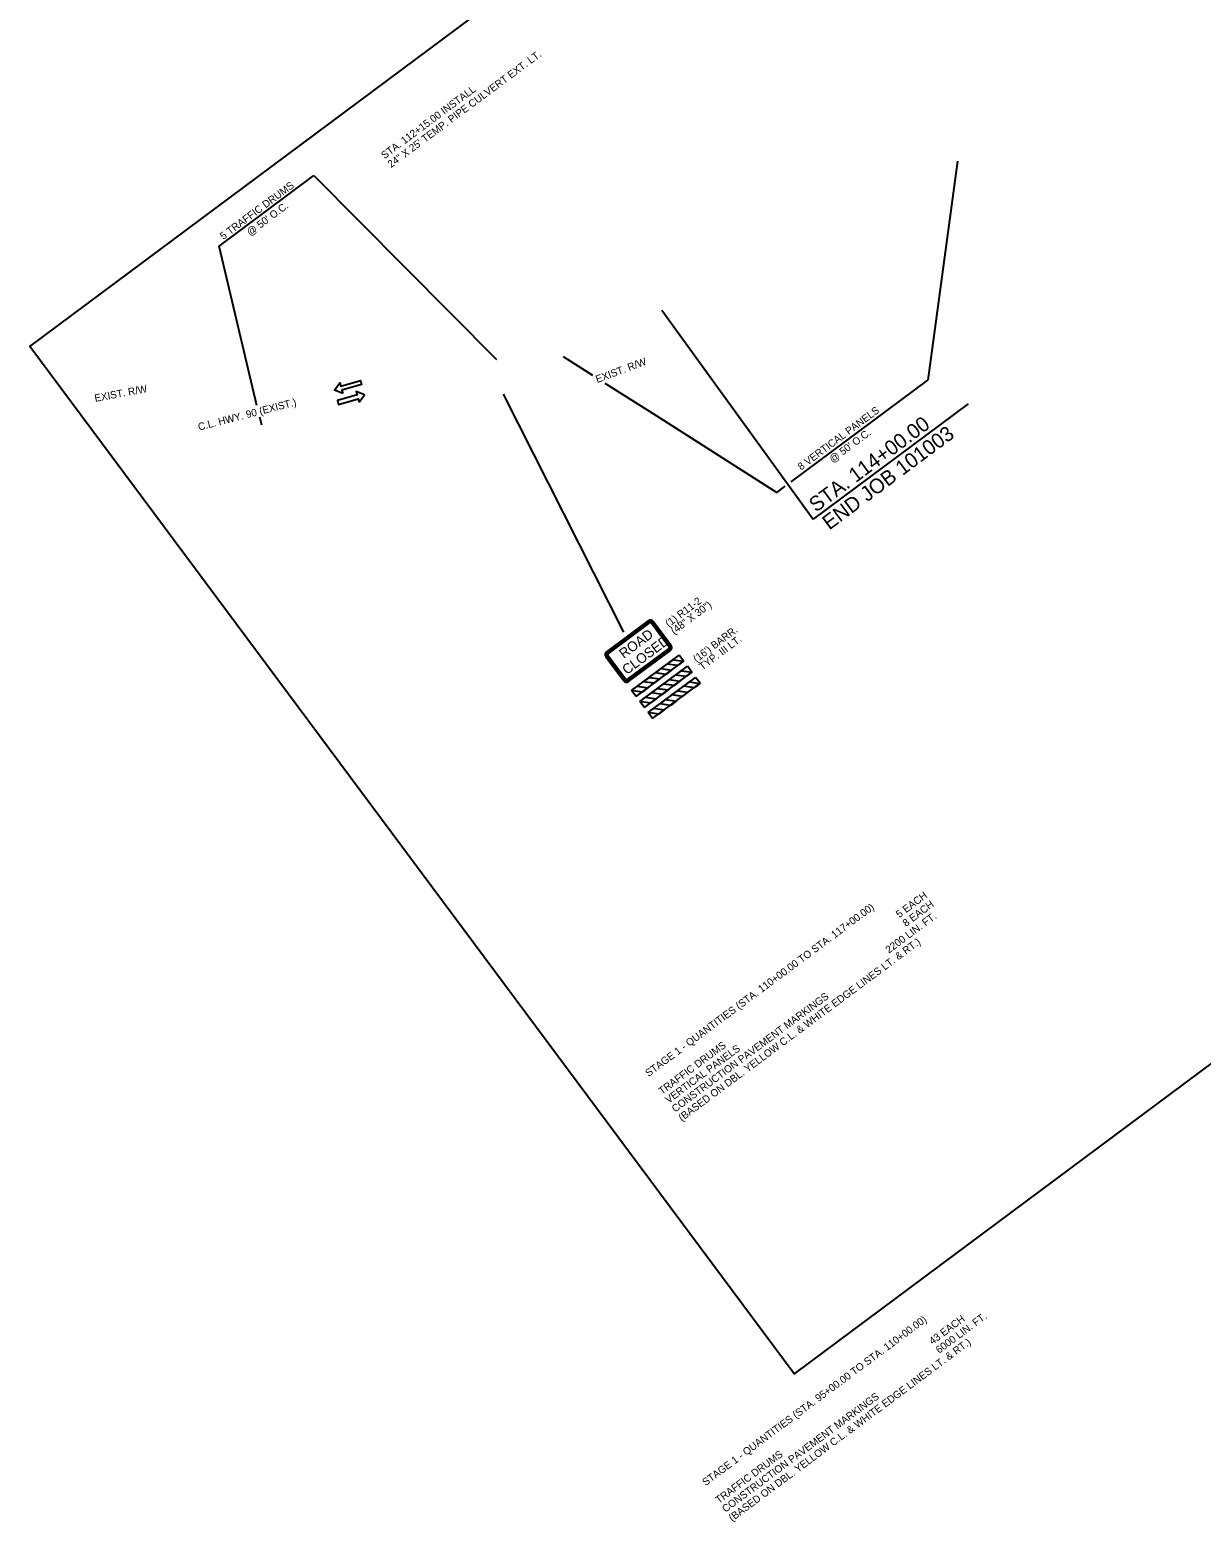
# Model space of a CAD drawing. Extents: x 1571137 to 1573037, y 731477 to 733451.
# Drawn here: x 1571137 to 1572087, y 731477 to 732687 of the extents above; entities that cross this region are included whole.
import ezdxf

# ---------------------------------------------------------------- set-up
doc = ezdxf.new("R2010")
doc.units = 0
for name, color, linetype in [('Level 3', 7, 'Continuous'), ('P_TC_Signs_Permanent', 7, 'Continuous'), ('R_Annotation', 7, 'Continuous'), ('R_Horz Alg Annot', 7, 'Continuous'), ('R_MOT', 7, 'Continuous'), ('R_ROW Annot', 7, 'Continuous')]:
    doc.layers.add(name, color=color, linetype=linetype)

msp = doc.modelspace()

# ---------------------------------------------------------------- linework, layer by layer
at = {"layer": 'Level 3'}
for p, q in [((1571625, 732151.3), (1571663.5, 732179.9)), ((1571667.1, 732175.1), (1571663.5, 732179.9)), ((1571628.6, 732146.4), (1571667.1, 732175.1)), ((1571631.7, 732142.3), (1571670.2, 732171)), ((1571635.3, 732137.5), (1571673.8, 732166.2)), ((1571667.1, 732175.1), (1571667.1, 732175.2)), ((1571673.8, 732166.2), (1571670.2, 732171)), ((1571673.8, 732166.2), (1571670.2, 732171)), ((1571638.3, 732133.4), (1571676.9, 732162)), ((1571641.9, 732128.5), (1571680.5, 732157.2)), ((1571680.5, 732157.2), (1571676.9, 732162)), ((1571628.6, 732146.4), (1571625, 732151.3)), ((1571635.3, 732137.5), (1571631.7, 732142.3)), ((1571641.9, 732128.5), (1571638.3, 732133.4))]:
    msp.add_line(p, q, dxfattribs=at)
for points in [[(1571644.3, 732165.6), (1571649, 732169.1), (1571657.4, 732167.9), (1571652.7, 732164.4)], [(1571653.9, 732172.8), (1571658.6, 732176.3), (1571667, 732175.1), (1571662.3, 732171.5)], [(1571660.6, 732163.8), (1571665.3, 732167.3), (1571673.7, 732166.1), (1571669, 732162.6)], [(1571625, 732151.3), (1571629.8, 732154.8), (1571638.2, 732153.6), (1571633.4, 732150)], [(1571634.6, 732158.4), (1571639.4, 732162), (1571647.8, 732160.7), (1571643.1, 732157.2)], [(1571650.9, 732156.6), (1571655.7, 732160.2), (1571664.1, 732158.9), (1571659.4, 732155.4)], [(1571667.2, 732154.9), (1571672, 732158.4), (1571680.4, 732157.1), (1571675.6, 732153.6)], [(1571631.7, 732142.3), (1571636.4, 732145.8), (1571644.8, 732144.6), (1571640.1, 732141.1)], [(1571641.3, 732149.5), (1571646.1, 732153), (1571654.5, 732151.8), (1571649.7, 732148.2)], [(1571648, 732140.5), (1571652.7, 732144), (1571661.1, 732142.8), (1571656.4, 732139.3)], [(1571657.6, 732147.7), (1571662.3, 732151.2), (1571670.7, 732150), (1571666, 732146.5)], [(1571638.3, 732133.4), (1571643.1, 732136.9), (1571651.5, 732135.7), (1571646.8, 732132.1)]]:
    msp.add_lwpolyline(points, close=True, dxfattribs=at)
at = {"layer": 'P_TC_Signs_Permanent'}
for p, q in [((1571638.6, 732208), (1571604.6, 732182.7)), ((1571639.1, 732207.3), (1571605.1, 732182)), ((1571639.8, 732206.4), (1571605.8, 732181.1)), ((1571655.5, 732186.6), (1571640.9, 732206.2)), ((1571656.5, 732187.4), (1571641.9, 732206.9)), ((1571657.1, 732187.8), (1571642.5, 732207.4)), ((1571604, 732178.7), (1571618.6, 732159.2)), ((1571604.7, 732179.2), (1571619.2, 732159.6)), ((1571605.6, 732179.9), (1571620.2, 732160.4)), ((1571621.3, 732160.2), (1571655.3, 732185.5)), ((1571622, 732159.2), (1571656, 732184.6)), ((1571622.5, 732158.6), (1571656.5, 732183.9))]:
    msp.add_line(p, q, dxfattribs=at)
for centre, radius, start, end in [((1571640.3, 732205.7), 2.8, 36.6576, 126.6576), ((1571640.3, 732205.7), 2, 36.6576, 126.6576), ((1571640.3, 732205.7), 0.8, 36.6576, 126.6576), ((1571606.3, 732180.4), 2.8, 126.6576, 216.6576), ((1571606.3, 732180.4), 2, 126.6576, 216.6576), ((1571606.3, 732180.4), 0.8, 126.6576, 216.6576), ((1571654.8, 732186.2), 0.8, 306.6576, 36.6576), ((1571654.8, 732186.2), 2, 306.6576, 36.6576), ((1571654.8, 732186.2), 2.8, 306.6576, 36.6576), ((1571620.8, 732160.8), 2.8, 216.6576, 306.6576), ((1571620.8, 732160.8), 2, 216.6576, 306.6576), ((1571620.8, 732160.8), 0.8, 216.6576, 306.6576)]:
    msp.add_arc(centre, radius, start, end, dxfattribs=at)
at = {"layer": 'R_Annotation'}
for p, q in [((1571889.2, 732580.5), (1571865.1, 732403)), ((1571290.6, 732511.6), (1571367.4, 732568.8)), ((1571367.4, 732568.8), (1571515.4, 732419.8)), ((1571321, 732382.3), (1571290.6, 732511.6)), ((1571649.5, 732459.7), (1571772.2, 732290.2)), ((1571569.6, 732422), (1571593.2, 732407)), ((1571603.3, 732400.6), (1571644.9, 732374.2)), ((1571754.4, 732320.6), (1571865.1, 732403)), ((1571520.8, 732391.6), (1571618.5, 732198.5)), ((1571897.8, 732383.7), (1571772.2, 732290.2)), ((1571325, 732366.4), (1571323.4, 732372.9)), ((1571644.9, 732374.2), (1571742.8, 732311.9)), ((1571742.8, 732311.9), (1571749.6, 732317))]:
    msp.add_line(p, q, dxfattribs=at)
at = {"layer": 'R_Horz Alg Annot'}
msp.add_lwpolyline([(1572536.7, 733221.6), (1573036.7, 732549.8), (1571756.9, 731597.3), (1571137, 732430.2), (1572086.8, 733137.2), (1572116.3, 733097.5), (1572258.8, 733203.6), (1572269.5, 733189.2), (1572284.1, 733200.1), (1572282.1, 733202.7), (1572344.4, 733249.1)], dxfattribs=at)
at = {"layer": 'R_MOT'}
for points in [[(1571390.9, 732392.2), (1571384, 732394.9), (1571388.4, 732400.9), (1571389.2, 732398.2), (1571405.1, 732402.7), (1571406, 732399.5), (1571390.1, 732394.9)], [(1571404, 732385.2), (1571408.4, 732391.1), (1571401.6, 732393.8), (1571402.3, 732391.1), (1571386.4, 732386.5), (1571387.4, 732383.3), (1571403.3, 732387.9)]]:
    msp.add_lwpolyline(points, close=True, dxfattribs=at)

# ---------------------------------------------------------------- texts
at = {"layer": 'P_TC_Signs_Permanent'}
for s, p in [('ROAD', (1571618.6, 732176.9)), ('CLOSED', (1571621.1, 732163.8))]:
    msp.add_text(s, height=8, rotation=36.6576, dxfattribs=at).set_placement(p)
at = {"layer": 'R_Annotation'}
for s, height, rotation, p in [('24" X 25\' TEMP. PIPE CULVERT EXT. LT.', 6, 36.6576, (1571429.9, 732574.8)), ('STA. 112+15.00 INSTALL', 6, 36.6576, (1571424.6, 732582)), ('5 TRAFFIC DRUMS ', 6, 36.6576, (1571293.9, 732516.5)), ("@ 50' O.C. ", 6, 36.6576, (1571315.6, 732519.6)), ('C.L. HWY. 90 (EXIST.)', 6, 14.5133, (1571274.2, 732362)), ('8 VERTICAL PANELS ', 6, 36.6576, (1571762.4, 732329.6)), ('STA. 114+00.00', 12, 36.6576, (1571774.5, 732295.4)), ('END JOB 101003', 12, 36.6576, (1571785.3, 732281)), ("@ 50' O.C. ", 6, 36.6576, (1571788, 732335.6)), ('(1) R11-2', 6, 36.8295, (1571655, 732202.4)), ('(48" X 30")', 6, 36.8295, (1571659.5, 732196.4)), ("(16') BARR.", 6, 36.8295, (1571677.6, 732173.8)), ('TYP. III LT.', 6, 36.8295, (1571682.4, 732167.4)), ('5 EACH', 6, 36.6576, (1571842.1, 731966.7)), ('STAGE 1 - QUANTITIES (STA. 110+00.00 TO STA. 117+00.00)', 6, 36.6576, (1571638.8, 731837.9)), ('8 EACH ', 6, 36.6576, (1571847.5, 731959.5)), ('2200 LIN. FT.', 6, 36.6576, (1571833.6, 731937.9)), ('(BASED ON DBL. YELLOW C.L. & WHITE EDGE LINES LT. & RT.)', 6, 36.6576, (1571665.7, 731801.8)), ('CONSTRUCTION PAVEMENT MARKINGS ', 6, 36.6576, (1571660.3, 731809)), ('TRAFFIC DRUMS', 6, 36.6576, (1571649.6, 731823.4)), ('VERTICAL PANELS ', 6, 36.6576, (1571655, 731816.2)), ('6000 LIN. FT.', 6, 36.6576, (1571874.4, 731613.5)), ('STAGE 1 - QUANTITIES (STA. 95+00.00 TO STA. 110+00.00)', 6, 36.6576, (1571685, 731506.2)), ('43 EACH', 6, 36.6576, (1571869, 731620.7)), ('(BASED ON DBL. YELLOW C.L. & WHITE EDGE LINES LT. & RT.)', 6, 36.6576, (1571706.5, 731477.3)), ('CONSTRUCTION PAVEMENT MARKINGS ', 6, 36.6576, (1571701.1, 731484.6)), ('TRAFFIC DRUMS', 6, 36.6576, (1571695.7, 731491.8))]:
    msp.add_text(s, height=height, rotation=rotation, dxfattribs=at).set_placement(p)
at = {"layer": 'R_ROW Annot'}
for rotation, p in [(20.5131, (1571597.1, 732400.6)), (10.7016, (1571190, 732385.3))]:
    msp.add_text('EXIST. R/W', height=6, rotation=rotation, dxfattribs=at).set_placement(p)

doc.saveas('drawing.dxf')
